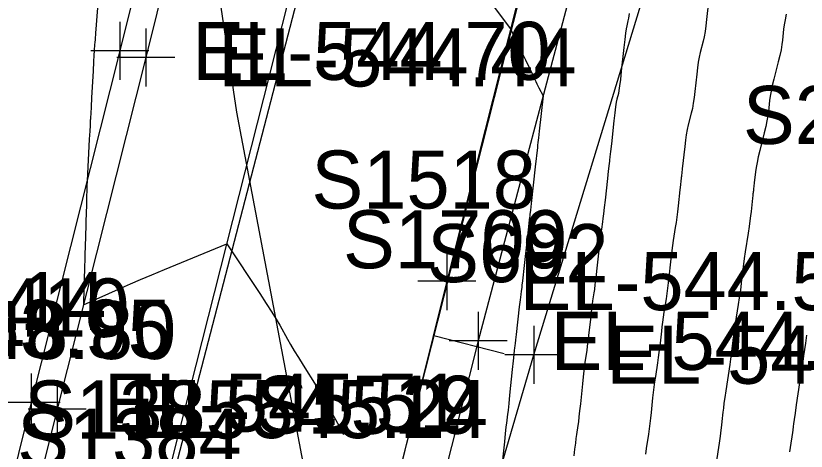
# Model space of a CAD drawing. Extents: x 1724534 to 1727318, y 657156 to 660047.
# Drawn here: x 1725485.5 to 1725540, y 659174.9 to 659204.9 of the extents above; entities that cross this region are included whole.
import ezdxf

# ---------------------------------------------------------------- set-up
doc = ezdxf.new("R2010")
doc.units = 0
for name, color, linetype in [('SURVEY - CENTERLINE - Preliminary', 7, 'Continuous'), ('SURVEY - CENTERLINE - Preliminary Text', 7, 'Continuous'), ('SURVEY - CONTOURS - Index with Text', 7, 'Continuous'), ('SURVEY - CONTOURS - Intermediate with optional Text', 7, 'Continuous'), ('SURVEY - DRAINAGE - Area Shapes', 7, 'Continuous'), ('SURVEY - DTM - Breaklines', 7, 'Continuous'), ('SURVEY - DTM - Breaklines - Points - Elevations', 7, 'Continuous'), ('SURVEY - DTM - Breaklines - Points - Locators', 7, 'Continuous'), ('SURVEY - DTM - Breaklines - Points - Numbers', 7, 'Continuous'), ('SURVEY - NON-TRANSPORTATION - Features - Points - Elevations', 7, 'Continuous'), ('SURVEY - ROADSIDE BARRIERS - Points - Elevations', 7, 'Continuous'), ('SURVEY - ROADSIDE BARRIERS - Points - Locators', 7, 'Continuous'), ('SURVEY - ROADSIDE BARRIERS - Points - Numbers', 7, 'Continuous'), ('SURVEY - ROADSIDE BARRIERS with Text', 7, 'Continuous'), ('SURVEY - TRANSPORTATION - Features', 7, 'Continuous'), ('SURVEY - TRANSPORTATION - Features - Points - Elevations', 7, 'Continuous'), ('SURVEY - TRANSPORTATION - Features - Points - Locators', 7, 'Continuous'), ('SURVEY - TRANSPORTATION - Features - Points - Numbers', 7, 'Continuous'), ('SURVEY - TRANSPORTATION - Roads', 7, 'Continuous'), ('SURVEY - TRANSPORTATION - Roads - Points - Elevations', 7, 'Continuous'), ('SURVEY - TRANSPORTATION - Roads - Points - Locators', 7, 'Continuous'), ('SURVEY - TRANSPORTATION - Roads - Points - Numbers', 7, 'Continuous'), ('SURVEY - UTILITIES - Fiber Optic Cable (Underground) with Text', 7, 'Continuous')]:
    doc.layers.add(name, color=color, linetype=linetype)

msp = doc.modelspace()

# ---------------------------------------------------------------- linework, layer by layer
at = {"layer": 'SURVEY - CENTERLINE - Preliminary'}
msp.add_line((1725628.749, 659634.745), (1725510.016, 659165.778), dxfattribs=at)
msp.add_line((1725628.749, 659634.745), (1725510.016, 659165.778), dxfattribs=at)
msp.add_line((1725628.749, 659634.745), (1725510.016, 659165.778), dxfattribs=at)
at = {"layer": 'SURVEY - CENTERLINE - Preliminary Text'}
msp.add_line((1725514.347, 659182.886), (1725519.195, 659181.659), dxfattribs=at)
at = {"layer": 'SURVEY - CONTOURS - Index with Text'}
for points in [[(1725491.212, 659206.085), (1725491.076, 659204.308), (1725491.031, 659203.724), (1725490.999, 659203.308), (1725490.98, 659203.058), (1725490.973, 659202.975), (1725490.973, 659202.975), (1725490.973, 659202.974), (1725490.973, 659202.972), (1725490.973, 659202.969), (1725490.973, 659202.965), (1725490.972, 659202.952), (1725490.971, 659202.94), (1725490.969, 659202.913), (1725490.966, 659202.872), (1725490.961, 659202.817), (1725490.949, 659202.65), (1725490.94, 659202.507), (1725490.923, 659202.206), (1725490.897, 659201.745), (1725490.863, 659201.125), (1725490.761, 659199.259), (1725490.728, 659198.643), (1725490.703, 659198.195), (1725490.687, 659197.914), (1725490.681, 659197.801), (1725490.675, 659197.723), (1725490.669, 659197.621), (1725490.655, 659197.37), (1725490.634, 659196.973), (1725490.604, 659196.428), (1725490.45, 659193.54), (1725490.441, 659193.205), (1725490.44, 659193.136), (1725490.438, 659193.075), (1725490.437, 659193.021), (1725490.435, 659192.973), (1725490.432, 659192.856), (1725490.429, 659192.764), (1725490.424, 659192.573), (1725490.416, 659192.285), (1725490.406, 659191.899), (1725490.375, 659190.74), (1725490.363, 659190.318), (1725490.352, 659189.922), (1725490.341, 659189.551), (1725490.331, 659189.205), (1725490.303, 659188.316), (1725490.293, 659188.007), (1725490.285, 659187.743), (1725490.278, 659187.526), (1725490.273, 659187.355), (1725490.262, 659186.961), (1725490.257, 659186.801), (1725490.251, 659186.615), (1725490.245, 659186.403), (1725490.237, 659186.166), (1725490.198, 659184.999), (1725492.831, 659186.178), (1725493.439, 659186.446), (1725494.136, 659186.746), (1725494.922, 659187.078), (1725495.796, 659187.442), (1725500.082, 659189.213), (1725502.35, 659185.789), (1725502.8, 659185.103), (1725503.179, 659184.509), (1725503.487, 659184.009), (1725503.723, 659183.603), (1725504.259, 659182.643), (1725504.477, 659182.261), (1725504.729, 659181.834), (1725505.015, 659181.363), (1725505.336, 659180.847), (1725506.237, 659179.413), (1725506.582, 659178.849), (1725506.941, 659178.232), (1725507.313, 659177.564), (1725507.7, 659176.842), (1725508.112, 659176.059)], [(1725540.02, 659182.92), (1725539.934, 659182.352), (1725539.87, 659181.923), (1725539.828, 659181.634), (1725539.808, 659181.484), (1725539.784, 659181.269), (1725539.764, 659181.119), (1725539.721, 659180.828), (1725539.657, 659180.396), (1725539.309, 659178.109), (1725539.222, 659177.534), (1725539.157, 659177.096), (1725539.115, 659176.795), (1725539.094, 659176.63), (1725539.068, 659176.372), (1725539.047, 659176.207), (1725539.004, 659175.904), (1725538.938, 659175.463), (1725538.851, 659174.884)]]:
    msp.add_lwpolyline(points, dxfattribs=at)
at = {"layer": 'SURVEY - CONTOURS - Intermediate with optional Text'}
for points in [[(1725518.015, 659206.185), (1725519.625, 659204.024), (1725520.06, 659203.094), (1725520.246, 659202.707), (1725520.351, 659202.49), (1725520.645, 659201.891), (1725520.752, 659201.671), (1725520.854, 659201.461), (1725520.95, 659201.261), (1725521.042, 659201.072), (1725521.278, 659200.579), (1725521.363, 659200.402), (1725521.441, 659200.241), (1725521.513, 659200.096), (1725521.578, 659199.967), (1725521.864, 659199.399), (1725521.597, 659196.973), (1725521.547, 659196.518), (1725521.511, 659196.193), (1725521.49, 659195.997), (1725521.482, 659195.929), (1725521.472, 659195.839), (1725521.325, 659194.504), (1725521.047, 659191.981), (1725520.996, 659191.522), (1725520.963, 659191.232), (1725520.948, 659191.11), (1725520.933, 659191.011), (1725520.919, 659190.892), (1725520.886, 659190.61), (1725520.836, 659190.164), (1725520.768, 659189.555), (1725520.563, 659187.715), (1725520.444, 659186.65), (1725520.409, 659186.355), (1725520.392, 659186.218), (1725520.369, 659186.064), (1725520.353, 659185.946), (1725520.325, 659185.708), (1725520.284, 659185.35), (1725520.23, 659184.872), (1725520.014, 659182.956), (1725519.972, 659182.592), (1725519.942, 659182.344), (1725519.925, 659182.212), (1725519.895, 659182.016), (1725519.877, 659181.869), (1725519.845, 659181.575), (1725519.799, 659181.134), (1725519.739, 659180.547), (1725519.56, 659178.784), (1725519.5, 659178.194), (1725519.453, 659177.746), (1725519.419, 659177.44), (1725519.398, 659177.277), (1725519.361, 659177.031), (1725519.34, 659176.87), (1725519.307, 659176.571), (1725519.26, 659176.135), (1725519.201, 659175.561), (1725518.965, 659173.271)], [(1725533.258, 659205.89), (1725533.135, 659204.666), (1725533.085, 659204.228), (1725533.028, 659203.831), (1725532.964, 659203.476), (1725532.893, 659203.162), (1725532.694, 659202.382), (1725532.623, 659202.07), (1725532.559, 659201.719), (1725532.501, 659201.33), (1725532.451, 659200.902), (1725532.325, 659199.71), (1725532.274, 659199.281), (1725532.216, 659198.888), (1725532.15, 659198.531), (1725532.077, 659198.21), (1725531.873, 659197.401), (1725531.799, 659197.081), (1725531.734, 659196.728), (1725531.675, 659196.342), (1725531.623, 659195.923), (1725531.453, 659194.376), (1725531.422, 659194.095), (1725531.402, 659193.918), (1725531.393, 659193.844), (1725531.384, 659193.784), (1725531.375, 659193.714), (1725531.356, 659193.545), (1725531.327, 659193.28), (1725531.287, 659192.918), (1725531.166, 659191.822), (1725531.12, 659191.421), (1725531.073, 659191.039), (1725531.024, 659190.675), (1725530.974, 659190.331), (1725530.838, 659189.437), (1725530.788, 659189.094), (1725530.74, 659188.736), (1725530.693, 659188.362), (1725530.648, 659187.972), (1725530.53, 659186.911), (1725530.484, 659186.52), (1725530.437, 659186.141), (1725530.387, 659185.774), (1725530.335, 659185.42), (1725530.194, 659184.492), (1725530.144, 659184.149), (1725530.098, 659183.816), (1725530.056, 659183.492), (1725530.019, 659183.178), (1725529.926, 659182.353), (1725529.889, 659182.037), (1725529.847, 659181.71), (1725529.8, 659181.37), (1725529.748, 659181.018), (1725529.602, 659180.062), (1725529.55, 659179.702), (1725529.501, 659179.336), (1725529.457, 659178.965), (1725529.416, 659178.588), (1725529.314, 659177.578), (1725529.273, 659177.2), (1725529.228, 659176.825), (1725529.179, 659176.452), (1725529.125, 659176.081), (1725528.974, 659175.094), (1725528.92, 659174.724)], [(1725527.796, 659205.08), (1725527.752, 659204.76), (1725527.714, 659204.567), (1725527.626, 659204.218), (1725527.588, 659204.027), (1725527.543, 659203.715), (1725527.49, 659203.283), (1725527.429, 659202.73), (1725527.257, 659201.094), (1725527.195, 659200.538), (1725527.141, 659200.099), (1725527.093, 659199.777), (1725527.052, 659199.57), (1725526.952, 659199.175), (1725526.911, 659198.971), (1725526.863, 659198.656), (1725526.808, 659198.228), (1725526.747, 659197.689), (1725526.572, 659196.102), (1725526.515, 659195.579), (1725526.473, 659195.203), (1725526.447, 659194.972), (1725526.438, 659194.888), (1725526.424, 659194.776), (1725526.399, 659194.558), (1725526.36, 659194.203), (1725526.306, 659193.711), (1725526.141, 659192.215), (1725526.084, 659191.701), (1725526.034, 659191.28), (1725525.994, 659190.954), (1725525.961, 659190.721), (1725525.886, 659190.224), (1725525.853, 659189.993), (1725525.813, 659189.673), (1725525.764, 659189.263), (1725525.708, 659188.764), (1725525.547, 659187.313), (1725525.49, 659186.812), (1725525.44, 659186.395), (1725525.398, 659186.065), (1725525.364, 659185.819), (1725525.281, 659185.278), (1725525.249, 659185.048), (1725525.211, 659184.762), (1725525.17, 659184.421), (1725525.124, 659184.025), (1725524.997, 659182.894), (1725524.952, 659182.497), (1725524.909, 659182.151), (1725524.871, 659181.857), (1725524.836, 659181.615), (1725524.749, 659181.039), (1725524.713, 659180.785), (1725524.673, 659180.455), (1725524.628, 659180.049), (1725524.578, 659179.568), (1725524.437, 659178.181), (1725524.387, 659177.697), (1725524.341, 659177.286), (1725524.299, 659176.946), (1725524.261, 659176.679), (1725524.167, 659176.062), (1725524.13, 659175.797), (1725524.089, 659175.463), (1725524.043, 659175.061), (1725523.993, 659174.59)], [(1725538.621, 659205.036), (1725538.538, 659204.648), (1725538.477, 659204.301), (1725538.437, 659203.996), (1725538.361, 659203.237), (1725538.321, 659202.931), (1725538.26, 659202.582), (1725538.176, 659202.191), (1725538.072, 659201.758), (1725537.763, 659200.545), (1725537.658, 659200.112), (1725537.574, 659199.723), (1725537.512, 659199.377), (1725537.472, 659199.075), (1725537.393, 659198.327), (1725537.353, 659198.024), (1725537.291, 659197.677), (1725537.207, 659197.285), (1725537.102, 659196.849), (1725536.793, 659195.627), (1725536.688, 659195.192), (1725536.604, 659194.801), (1725536.541, 659194.457), (1725536.5, 659194.157), (1725536.419, 659193.419), (1725536.392, 659193.173), (1725536.371, 659192.988), (1725536.356, 659192.864), (1725536.348, 659192.8), (1725536.335, 659192.712), (1725536.327, 659192.651), (1725536.313, 659192.533), (1725536.293, 659192.357), (1725536.267, 659192.125), (1725536.191, 659191.43), (1725536.157, 659191.141), (1725536.111, 659190.797), (1725536.054, 659190.397), (1725535.986, 659189.941), (1725535.79, 659188.651), (1725535.723, 659188.196), (1725535.666, 659187.799), (1725535.621, 659187.46), (1725535.587, 659187.18), (1725535.513, 659186.509), (1725535.479, 659186.228), (1725535.433, 659185.886), (1725535.376, 659185.483), (1725535.307, 659185.021), (1725535.107, 659183.706), (1725535.039, 659183.251), (1725534.984, 659182.869), (1725534.942, 659182.563), (1725534.913, 659182.331), (1725534.855, 659181.811), (1725534.826, 659181.578), (1725534.784, 659181.269), (1725534.728, 659180.883), (1725534.456, 659179.086), (1725534.386, 659178.618), (1725534.329, 659178.216), (1725534.286, 659177.88), (1725534.255, 659177.609), (1725534.191, 659176.975), (1725534.16, 659176.704), (1725534.116, 659176.364), (1725534.059, 659175.957), (1725533.988, 659175.482), (1725533.781, 659174.125)]]:
    msp.add_lwpolyline(points, dxfattribs=at)
at = {"layer": 'SURVEY - DRAINAGE - Area Shapes'}
msp.add_lwpolyline([(1725457.865, 659006.777), (1725413.857, 659016.262), (1725297.605, 659050.843), (1725314.042, 659296.608), (1725386.76, 659493.901), (1725483.401, 659755.229), (1725623.949, 659732.704), (1725676.22, 659724.326), (1725634.82, 659466.017), (1725543.324, 659353.721), (1725499.683, 659185.923), (1725479.088, 659106.738)], close=True, dxfattribs=at)
at = {"layer": 'SURVEY - DTM - Breaklines'}
msp.add_lwpolyline([(1725504.884, 659250.966), (1725498.725, 659226.793), (1725492.704, 659202.503), (1725486.609, 659178.27), (1725480.544, 659153.955), (1725474.624, 659129.616), (1725468.741, 659105.278), (1725462.975, 659080.964), (1725457.482, 659056.509), (1725452.226, 659031.922), (1725447.641, 659009.959), (1725446.425, 659003.851), (1725441.811, 658979.15), (1725437.527, 658954.376), (1725432.503, 658922.481), (1725434.197, 658921.722)], dxfattribs=at)
at = {"layer": 'SURVEY - DTM - Breaklines - Points - Locators'}
for p, q in [((1725492.704, 659204.503), (1725492.704, 659200.503)), ((1725494.704, 659202.503), (1725490.704, 659202.503)), ((1725486.609, 659180.27), (1725486.609, 659176.27)), ((1725488.609, 659178.27), (1725484.609, 659178.27))]:
    msp.add_line(p, q, dxfattribs=at)
at = {"layer": 'SURVEY - ROADSIDE BARRIERS - Points - Locators'}
for p, q in [((1725521.221, 659183.564), (1725521.221, 659179.564)), ((1725523.221, 659181.564), (1725519.221, 659181.564))]:
    msp.add_line(p, q, dxfattribs=at)
at = {"layer": 'SURVEY - ROADSIDE BARRIERS with Text'}
msp.add_lwpolyline([(1725454.307, 658763.664), (1725456.988, 658788.398), (1725459.975, 658813.106), (1725462.961, 658837.817), (1725466.031, 658862.66), (1725469.198, 658887.437), (1725472.364, 658912.252), (1725475.489, 658936.998), (1725478.578, 658961.799), (1725481.795, 658986.471), (1725485.277, 659011.185), (1725489.239, 659035.685), (1725493.561, 659060.194), (1725498.271, 659084.816), (1725503.177, 659108.92), (1725508.576, 659133.257), (1725514.221, 659157.599), (1725521.221, 659181.564), (1725529.697, 659209.302)], dxfattribs=at)
at = {"layer": 'SURVEY - TRANSPORTATION - Features'}
for points in [[(1725537.281, 659258.937), (1725530.962, 659234.747), (1725524.817, 659210.531), (1725517.386, 659182.521), (1725511.279, 659158.31), (1725505.645, 659133.966), (1725500.348, 659109.577), (1725495.279, 659085.33), (1725490.855, 659060.693), (1725486.478, 659036.153), (1725482.443, 659011.591), (1725478.797, 658986.889), (1725475.825, 658962.14), (1725472.769, 658937.341), (1725469.208, 658912.632), (1725466.187, 658887.82), (1725463.008, 658863.047)], [(1725506.673, 659250.514), (1725500.512, 659226.334), (1725494.493, 659202.049), (1725488.389, 659177.819), (1725482.327, 659153.516), (1725476.395, 659129.191), (1725470.514, 659104.862), (1725464.748, 659080.55), (1725459.259, 659056.109), (1725454.008, 659031.549), (1725449.429, 659009.612), (1725448.213, 659003.504), (1725443.603, 658978.829), (1725439.325, 658954.082), (1725434.304, 658922.209), (1725434.197, 658921.722)]]:
    msp.add_lwpolyline(points, dxfattribs=at)
at = {"layer": 'SURVEY - TRANSPORTATION - Features - Points - Locators'}
for p, q in [((1725494.493, 659204.049), (1725494.493, 659200.049)), ((1725496.493, 659202.049), (1725492.493, 659202.049)), ((1725517.386, 659184.521), (1725517.386, 659180.521)), ((1725519.386, 659182.521), (1725515.386, 659182.521)), ((1725488.389, 659179.819), (1725488.389, 659175.819)), ((1725490.389, 659177.819), (1725486.389, 659177.819))]:
    msp.add_line(p, q, dxfattribs=at)
at = {"layer": 'SURVEY - TRANSPORTATION - Roads'}
for points in [[(1725533.446, 659258.339), (1725527.51, 659235.091), (1725524.059, 659221.528), (1725521.595, 659211.838), (1725515.243, 659186.636), (1725511.368, 659171.118), (1725509.433, 659163.358), (1725501.913, 659132.272), (1725496.037, 659106.962)], [(1725435.76, 658873.112), (1725439.371, 658898.842), (1725439.657, 658900.819), (1725445.023, 658936.389), (1725447.926, 658954.139), (1725448.261, 658956.109), (1725453.558, 658985.616), (1725453.93, 658987.58), (1725458.117, 659009.159), (1725458.517, 659011.117), (1725466.292, 659048.286), (1725466.718, 659050.238), (1725471.114, 659069.737), (1725478.393, 659100.872), (1725479.306, 659104.764), (1725484.9, 659128.087), (1725485.373, 659130.029), (1725489.666, 659147.5), (1725494.922, 659168.852), (1725495.411, 659170.791), (1725504.745, 659207.606), (1725509.226, 659225.033), (1725509.717, 659226.971)]]:
    msp.add_lwpolyline(points, dxfattribs=at)
at = {"layer": 'SURVEY - TRANSPORTATION - Roads - Points - Locators'}
for p, q in [((1725515.243, 659188.636), (1725515.243, 659184.636)), ((1725517.243, 659186.636), (1725513.243, 659186.636))]:
    msp.add_line(p, q, dxfattribs=at)
at = {"layer": 'SURVEY - UTILITIES - Fiber Optic Cable (Underground) with Text'}
msp.add_lwpolyline([(1725493.518, 659243.033), (1725493.322, 659242.827), (1725497.949, 659217.072), (1725500.753, 659198.279), (1725509.549, 659151.809), (1725515.229, 659134.254)], dxfattribs=at)

# ---------------------------------------------------------------- texts
at = {"layer": 'SURVEY - DTM - Breaklines - Points - Elevations'}
for s, p in [('EL-544.70', (1725497.704, 659200.503)), ('EL-563.95', (1725471.542, 659181.359)), ('EL-545.51', (1725491.609, 659176.27))]:
    msp.add_text(s, height=4, dxfattribs=at).set_placement(p)
at = {"layer": 'SURVEY - DTM - Breaklines - Points - Numbers'}
for s, p in [('S2208', (1725535.636, 659196.09)), ('S114', (1725479.273, 659183.27))]:
    msp.add_text(s, height=4, dxfattribs=at).set_placement(p)
at = {"layer": 'SURVEY - NON-TRANSPORTATION - Features - Points - Elevations'}
msp.add_text('EL-548.80', height=4, dxfattribs=at).set_placement((1725471.906, 659181.267))
at = {"layer": 'SURVEY - ROADSIDE BARRIERS - Points - Elevations'}
msp.add_text('EL-546.28', height=4, dxfattribs=at).set_placement((1725526.221, 659179.564))
at = {"layer": 'SURVEY - ROADSIDE BARRIERS - Points - Numbers'}
msp.add_text('S692', height=4, dxfattribs=at).set_placement((1725513.885, 659186.564))
at = {"layer": 'SURVEY - TRANSPORTATION - Features - Points - Elevations'}
for s, p in [('EL-544.44', (1725499.493, 659200.049)), ('EL-544.52', (1725522.386, 659180.521)), ('EL-545.24', (1725493.389, 659175.819))]:
    msp.add_text(s, height=4, dxfattribs=at).set_placement(p)
at = {"layer": 'SURVEY - TRANSPORTATION - Features - Points - Numbers'}
for s, p in [('S1709', (1725508.083, 659187.521)), ('S410', (1725480.88, 659182.819))]:
    msp.add_text(s, height=4, dxfattribs=at).set_placement(p)
at = {"layer": 'SURVEY - TRANSPORTATION - Roads - Points - Elevations'}
msp.add_text('EL-544.51', height=4, dxfattribs=at).set_placement((1725520.243, 659184.636))
at = {"layer": 'SURVEY - TRANSPORTATION - Roads - Points - Numbers'}
for s, p in [('S1518', (1725505.908, 659191.636)), ('S1519', (1725502.065, 659176.118)), ('S1385', (1725486.123, 659175.791)), ('S1384', (1725485.634, 659173.852))]:
    msp.add_text(s, height=4, dxfattribs=at).set_placement(p)

doc.saveas('drawing.dxf')
